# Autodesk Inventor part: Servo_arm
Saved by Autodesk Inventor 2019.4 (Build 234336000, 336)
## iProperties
Created: 2020-02
Part Number: Servo_arm
Material: Generic
Document SubType Name: Modeling
Designer: Administrator
Density: 1 g/cm^3
Appearance: Default
Title: Servo_arm v5
Author: Administrator
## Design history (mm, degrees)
feature "Body1"
body "Solid1"
